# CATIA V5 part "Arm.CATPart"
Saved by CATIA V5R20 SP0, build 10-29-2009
Part number: Part1
Material "Plastic": density 1200 kg/m3, Young's modulus 2.2e+09 Pa, Poisson ratio 0.38, thermal expansion 6.84e-05 1/K
Bounding box of the stored display mesh (mm): x -46.402 to 0, y -86.485 to 14.997, z -29.997 to 131.328
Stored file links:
  C:\Users\user\SkyDrive\Stuff\cad\Instructables\Hand adapter\CATIA V5, STEP ,IGES Files\Arm.CATPart
  C:\Program Files\Dassault Systemes\B20\win_b64\reffiles\standard\MetricThinPitch.txt
  C:\Program Files\Dassault Systemes\B20\win_b64\startup\materials\Catalog.CATMaterial
  C:\Program Files\Dassault Systemes\B20\win_b64\reffiles\standard\MetricThickPitch.txt
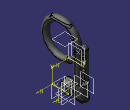
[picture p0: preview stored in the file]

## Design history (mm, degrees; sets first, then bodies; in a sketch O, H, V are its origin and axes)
Body1 (main body), material "Plastic"
  Sketch1 on xy-plane, origin (0, 0, 0), H (1, 0, 0), V (0, 1, 0)
    circle A1 centre (-31.4018, 0) radius 15
    radius A1 = 15
  Pad1: profile Sketch1, direction (0, 0, 1), length 10
  Sketch2 on end face of Pad1, origin (0, 0, 10), H (1, 0, 0), V (0, 1, 0)
    circle A1 centre (-23.9018, 0) radius 7.5
    point P1 (-23.9018, 0)
    circle A2 centre (-38.9018, 0) radius 7.5
    point P2 (-38.9018, 0)
    point P3 (-31.4018, 0)
    reference projected circle E1 centre (-31.4018, 0) radius 15 from edge [face of Pad1 from Sketch1.A1 | end face of Pad1]
    radius A1 = 7.5
    radius A2 = 7.5
    coincidence: P1 H, P2 H, P3 H
    tangency: A2 A1
    concentricity: P3 E1
    equidistance: P2 P1 P3
  Pad2: profile Sketch2, direction (0, 0, 1), length 65
  Plane1: type Offset, RefPlane zx-plane, Offset -7.5
  Sketch3 on Plane1, origin (0, -7.5, 0), H (-1, 0, 0), V (0, 0, 1)
    reference projected line E1 (16.4018, 10) -> (31.4018, 10) from edge [end face of Pad1 | face of Pad2 from Sketch2.A1]
    construction line L1 (31.4018, 75) -> (31.4018, 21.2562)
    spline S1 through (31.4018, 42.5) (36.4018, 50) (31.4018, 57.5) (26.4018, 50) (31.4018, 42.5)
    construction line L2 (93.6923, 50) -> (-93.4071, 50)
    construction line L3 (100.8473, 35) -> (-86.2521, 35)
    spline S2 through (31.4018, 31) (34.9018, 35) (31.4018, 39) (27.9018, 35) (31.4018, 31)
    line L4 (33.9018, 25) -> (28.9018, 25)
    line L5 (28.9018, 25) -> (28.9018, 15)
    line L6 (28.9018, 15) -> (33.9018, 15)
    line L7 (33.9018, 15) -> (33.9018, 25)
    construction line L8 (109.543, 20) -> (-92.7825, 20)
    point P16 (31.4018, 65)
    point P17 (31.4018, 60.9585)
    point P18 (34.9018, 62.9793)
    point P19 (34.9018, 67.0207)
    point P20 (31.4018, 69.0415)
    point P21 (27.9018, 67.0207)
    point P22 (27.9018, 62.9793)
    point P23 (33.1518, 61.9689)
    line L9 (31.4018, 60.9585) -> (34.9018, 62.9793)
    line L10 (34.9018, 62.9793) -> (34.9018, 67.0207)
    line L11 (34.9018, 67.0207) -> (31.4018, 69.0415)
    line L12 (31.4018, 69.0415) -> (27.9018, 67.0207)
    line L13 (27.9018, 67.0207) -> (27.9018, 62.9793)
    line L14 (27.9018, 62.9793) -> (31.4018, 60.9585)
    construction line L15 (31.4018, 65) -> (33.1518, 61.9689)
    construction circle A1 centre (31.4018, 65) radius 4.0415
    construction arc A2 centre (27.9018, 67.0207) radius 4.0415 from (31.4018, 69.0415) to (27.9018, 62.9793) cw
    construction arc A3 centre (34.9018, 62.9793) radius 4.0415 from (34.9018, 67.0207) to (31.4018, 60.9585) ccw
    point P24 (31.4018, 42.5)
    point P25 (31.4018, 57.5)
    point P26 (31.4018, 42.5)
    point P27 (36.4018, 50)
    point P28 (26.4018, 50)
    point P29 (34.9018, 35)
    point P30 (27.9018, 35)
    point P31 (31.4018, 39)
    point P32 (31.4018, 31)
    point P33 (31.4018, 31)
    distance P27 P28 = 10
    distance P25 P26 = 15
    distance P29 P30 = 7
    distance P31 P32 = 8
    length L4 = 5
    distance L4 L6 = 10
    distance L8 E1 = 10
    distance L3 L8 = 15
    distance L2 L3 = 15
    length L15 = 3.5
    distance P16 L2 = 15
    vertical: L1 V, L5 V, L7 V
    coincidence: P24 L1, P25 L1, P26 P24, P27 L2, P28 L2, P29 L3, P30 L3, P32 P33, P32 L1, P16 L1, A1 P17, A1 P18, A1 P19, A1 P20, A1 P21, A1 P22, A2 P16, A3 P16, P20 L1
    symmetry: P27 P28 L1, P25 P26 L2, P31 P32 L3, P29 P30 L1, L7 L5 L1, L4 L6 L8
    horizontal: L2 H, L4 H, L6 H, L8 H
    midpoint: P23 L9
    parallelism: L9 L12
  Pocket1: profile Sketch3, direction (0, 1, 0), through (limit type 3)
  Plane2: type Offset, RefPlane zx-plane, Offset -25
  Sketch4 on end face of Pad2, origin (0, 0, 75), H (1, 0, 0), V (0, 1, 0)
    point P1 (-23.9018, 0)
    reference projected circle E1 centre (-23.9018, 0) radius 7.5 from edge [face of Pad2 from Sketch2.A1 | end face of Pad2]
    concentricity: E1 P1
  Sketch5 on start face of Pad1, origin (0, 0, 0), H (1, 0, 0), V (0, -1, 0)
    circle A1 centre (-31.4018, 0) radius 15
    reference projected circle E1 centre (-31.4018, 0) radius 15 from edge [start face of Pad1 | face of Pad1 from Sketch1.A1]
    radius A1 = 15
    concentricity: A1 E1
  Sketch6 on start face of Pad1, origin (0, 0, 0), H (1, 0, 0), V (0, -1, 0)
    point P1 (-31.4018, 0)
    reference projected circle E1 centre (-31.4018, 0) radius 15 from edge [start face of Pad1 | face of Pad1 from Sketch1.A1]
    coincidence: P1 H
    concentricity: P1 E1
  Plane3: type OffsetPt, RefPlane yz-plane, RefPoint Sketch6
  Sketch7 on Plane3, origin (-31.4018, 0, 0), H (0, 1, 0), V (0, 0, 1)
    line L1 (0, 0) -> (0, -15)
    reference projected point E1 (0, 0) from Sketch6
    line L2 (0, -15) -> (-40, -15)
    length L1 = 15
    length L2 = 40
    vertical: L1 V
    coincidence: E1 L1
    horizontal: L2 H
  Rib1: profile Sketch5, centre curve Sketch7
  Plane4: type OffsetPt, RefPlane yz-plane, RefPoint Sketch4
  Sketch8 on end face of Pad2, origin (0, 0, 75), H (1, 0, 0), V (0, 1, 0)
    circle A1 centre (-23.9018, 0) radius 7.5
    point P1 (-23.9018, 0)
    reference projected point E1 (-23.9018, 0) from Sketch4
    radius A1 = 7.5
    coincidence: P1 H
    concentricity: E1 A1
  Sketch9 on Plane4, origin (-23.9018, 0, 0), H (0, 1, 0), V (0, 0, 1)
    arc A1 centre (-39.7571, 84.4017) radius 40 from (0, 80) to (-20, 49.6215) ccw
    construction line L1 (0, 139.5959) -> (0, 51.5037)
    point P2 (0, 139.5959)
    reference projected point E1 (0, 75) from Sketch4
    line L2 (0, 75) -> (0, 80)
    point P4 (0, 75)
    point P5 (0, 80)
    reference projected point E2 (0, 75) from Sketch4
    point P6 (-20, 49.6215)
    point P7 (0, 80)
    radius A1 = 40
    length L2 = 5
    distance P6 L1 = 20
    coincidence: P2 V, L1 E1, P4 L1, P5 A1, P4 E2, L1 P7, P5 P7
    vertical: L1 V, L2 V
  Rib2: profile Sketch8, centre curve Sketch9
  Sketch10 on face of Rib2, origin (0, 7.9366, 0.4422), H (-1, 0, 0), V (0, -0.4939, 0.8695)
    arc A1 centre (23.9018, 56.5603) radius 7.5 from (23.9018, 64.0603) to (23.9018, 49.0603) ccw
    point P1 (23.9018, 56.5603)
    reference projected circle E1 centre (23.9018, 56.5603) radius 7.5 from edge [face of Rib2 | face of Rib2]
    line L1 (23.9018, 64.0603) -> (23.9018, 49.0603)
    point P2 (23.9018, 52.8966)
    point P3 (23.9018, 60.2239)
    radius A1 = 7.5
    concentricity: A1 E1
    vertical: L1 V
    equidistance: P2 P3 P1
  Shaft1: profile Sketch10, axis Sketch10.L1, angle 360
  Sketch11 on end face of Pad2, origin (0, 0, 75), H (1, 0, 0), V (0, 1, 0)
    line L1 (-46.4018, 0) -> (-31.4018, 0)
    arc A1 centre (-38.9018, 0) radius 7.5 from (-31.4018, 0) to (-46.4018, 0) ccw
    point P1 (-38.9018, 0)
    reference projected circle E1 centre (-38.9018, 0) radius 7.5 from edge [face of Pad2 from Sketch2.A2 | end face of Pad2]
    radius A1 = 7.5
    horizontal: L1 H
    coincidence: P1 L1
    concentricity: A1 E1
  Shaft2: profile Sketch11, axis Sketch11.L1, angle 180
  Sketch12 on face of Rib1, origin (0, -40, 0), H (1, 0, 0), V (0, 0, 1)
    point P1 (-31.4018, -15)
    reference projected circle E1 centre (-31.4018, -15) radius 15 from edge [face of Rib1 | face of Rib1]
    concentricity: P1 E1
  Plane5: type OffsetPt, RefPlane xy-plane, RefPoint Sketch12
  Plane6: type Offset, RefPlane Plane3, Offset -15
  Plane7: type Offset, RefPlane Plane4, Offset 7.5
  Sketch13 on Plane7, origin (-16.4018, 0, 0), H (0, 1, 0), V (0, 0, 1)
    line L1 (-63.5987, 125.8143) -> (-13.5987, 125.8143)
    line L2 (-13.5987, 125.8143) -> (-13.5987, 120.8143)
    line L3 (-13.5987, 120.8143) -> (-63.5987, 120.8143)
    line L4 (-63.5987, 120.8143) -> (-63.5987, 125.8143)
    length L1 = 50
    length L2 = 5
    horizontal: L1 H, L3 H
    vertical: L2 V, L4 V
  Pocket2: profile Sketch13, direction (-1, 0, 0), length 8
  Fillet1: radius 6, on edge [face of Rib1 | face of Rib1]
  Sketch14 on Plane6, origin (-46.4018, 0, 0), H (0, 1, 0), V (0, 0, 1)
    line L1 (-15, -2.5) -> (-40, -2.5)
    line L2 (-40, -2.5) -> (-40, -27.5)
    line L3 (-40, -27.5) -> (-15, -27.5)
    line L4 (-15, -27.5) -> (-15, -2.5)
    point P2 (-40, -2.5)
    point P3 (-40, -27.5)
    reference projected point E1 (-40, -15) from Sketch12.P1
    length L2 = 25
    length L3 = 25
    horizontal: L1 H, L3 H
    vertical: L2 V, L4 V
    equidistance: P3 P2 E1
    coincidence: L2 E1
  Pocket3: profile Sketch14, direction (1, 0, 0), length 5
  Sketch15 on Plane7, origin (-16.4018, 0, 0), H (0, 1, 0), V (0, 0, 1)
    reference projected point E1 (-40, -15) from Sketch12.P1
    line L1 (-40, -2.5) -> (-15, -2.5)
    line L2 (-15, -2.5) -> (-15, -27.5)
    line L3 (-15, -27.5) -> (-40, -27.5)
    line L4 (-40, -27.5) -> (-40, -2.5)
    length L2 = 25
    length L1 = 25
    horizontal: L1 H, L3 H
    vertical: L2 V, L4 V
    midpoint: E1 L4
    coincidence: E1 L4
  Pocket4: profile Sketch15, direction (-1, 0, 0), length 5
  Sketch16 on end face of Pocket3, origin (-41.4018, -22.9671, -18.1896), H (0, 1, 0), V (0, 0, -1)
    point P1 (-4.5329, -3.1896)
    reference projected line E1 (-17.0329, -14.37) -> (-17.0329, 7.9907) from edge [end face of Pocket3 | face of Rib1]
    reference projected line E2 (7.9671, -13.9039) -> (7.9671, 7.9907) from edge [face of Rib1 | face of Pocket3 from Sketch14.L4]
    reference projected line E3 (-17.0329, 7.9907) -> (7.9671, 7.9907) from edge [end face of Pocket3 | face of Rib1]
    reference projected line E4 (-17.0329, -14.37) -> (7.3147, -14.37) from edge [face of Rib1 | end face of Pocket3]
    equidistance: E1 E2 P1, E3 E4 P1
  Hole1: placed by Sketch16, at (-41.4018, -27.5, -15) direction (1, 0, 0), diameter 8, through (limit type 3)
  Sketch17 on Plane7, origin (-16.4018, 0, 0), H (0, 1, 0), V (0, 0, 1)
    point P1 (0, 75)
    point P2 (4, 75)
    point P3 (2, 78.4641)
    point P4 (-2, 78.4641)
    point P5 (-4, 75)
    point P6 (-2, 71.5359)
    point P7 (2, 71.5359)
    point P8 (3, 76.7321)
    line L1 (4, 75) -> (2, 78.4641)
    line L2 (2, 78.4641) -> (-2, 78.4641)
    line L3 (-2, 78.4641) -> (-4, 75)
    line L4 (-4, 75) -> (-2, 71.5359)
    line L5 (-2, 71.5359) -> (2, 71.5359)
    line L6 (2, 71.5359) -> (4, 75)
    construction line L7 (0, 75) -> (3, 76.7321)
    construction circle A1 centre (0, 75) radius 4
    construction arc A2 centre (-2, 71.5359) radius 4 from (-4, 75) to (2, 71.5359) cw
    construction arc A3 centre (2, 78.4641) radius 4 from (-2, 78.4641) to (4, 75) ccw
    reference projected line E1 (-15, 10) -> (15, 10) from edge [face of Rib1 | end face of Pad1]
    point P9 (-15, 10)
    point P10 (15, 10)
    radius A2 = 4
    distance P1 E1 = 65
    coincidence: P1 V, A1 P2, A1 P3, A1 P4, A1 P5, A1 P6, A1 P7, A2 P1, A3 P1
    midpoint: P8 L1
    parallelism: L1 L4, L5 E1
    equidistance: P10 P9 P1
  Pocket5: profile Sketch17, direction (-1, 0, 0), length 10
  Sketch18 on Plane7, origin (-16.4018, 0, 0), H (0, 1, 0), V (0, 0, 1)
    circle A1 centre (-5, 104.5804) radius 2.5
    point P1 (-5, 104.5804)
    construction line L1 (0, 95.8845) -> (0, 52.9037)
    point P2 (0, 95.8845)
    reference projected point E1 (0, 75) from Sketch4
    radius A1 = 2.5
    distance P1 E1 = 30
    distance P1 L1 = 5
    coincidence: P2 V
    vertical: L1 V
  Pad3: profile Sketch18, direction (1, 0, 0), length 5, mirrored extent
  Sketch19 on end face of Pad3, origin (-11.4018, 0, 0), H (0, 1, 0), V (0, 0, 1)
    projected circle E1 centre (-5, 104.5804) radius 2.5 from edge [face of Pad3 from Sketch18.A1 | end face of Pad3]
    projected arc E2 centre (-5, 104.5804) radius 2.5 from (-5, 107.0804) to (-5, 102.0804) ccw from edge [face of Pad3 from Sketch18.A1 | end face of Pad3]
    line L1 (-5, 107.0804) -> (-5, 102.0804)
    point P1 (-5, 102.0804)
    point P2 (-5, 107.0804)
    point P3 (-5, 107.0804)
    point P4 (-5, 102.0804)
    vertical: L1 V
    coincidence: L1 P1, L1 P2, E1 P3, E1 P4, P1 P4, P2 P3
  Shaft3: profile Sketch19, axis Sketch19.L1, angle 180
  Fillet2: radius 3, on edge [face of Rib1 | face of Rib1]
  Fillet3: radius 3, on edge [face of Rib1 | face of Rib1]
  Sketch20 on Plane7, origin (-16.4018, 0, 0), H (0, 1, 0), V (0, 0, 1)
    arc A1 centre (0, 65) radius 3 from (2.958, 65.5) to (-2.958, 65.5) ccw
    point P1 (0, 65)
    line L1 (-4, 65.5) -> (-2.958, 65.5)
    line L2 (4, 65.5) -> (4, 64.5)
    line L3 (4, 64.5) -> (2.958, 64.5)
    line L4 (-4, 64.5) -> (-4, 65.5)
    point P4 (4, 64.5)
    point P5 (-4, 64.5)
    reference projected line E1 (-15, 10) -> (15, 10) from edge [face of Rib1 | end face of Pad1]
    point P9 (2.958, 65.5)
    arc A2 centre (0, 65) radius 3 from (-2.958, 64.5) to (2.958, 64.5) ccw
    point P11 (-2.958, 64.5)
    line L5 (-2.958, 64.5) -> (-4, 64.5)
    line L6 (2.958, 65.5) -> (4, 65.5)
    radius A1 = 3
    length L2 = 1
    distance E1 P1 = 55
    distance P4 P5 = 8
    coincidence: P1 V, L1 P9, L3 P11, A1 A2, L3 L5, L1 L6
    horizontal: L1 H, L3 H, L5 H, L6 H
    vertical: L2 V, L4 V
    equidistance: L4 L2 P1, L1 L3 P1
  Pocket6: profile Sketch20, direction (-1, 0, 0), length 10
  Plane8: type Offset, RefPlane Plane5, Offset 94
  Sketch21 on Plane8, origin (0, 0, 79), H (1, 0, 0), V (0, 1, 0)
    line L1 (-31.6518, 1) -> (-31.1518, 1)
    line L2 (-31.1518, 1) -> (-31.1518, -1)
    line L3 (-31.1518, -1) -> (-31.6518, -1)
    line L4 (-31.6518, -1) -> (-31.6518, 1)
    reference projected point E1 (-31.4018, 0) from Sketch6
    reference projected point E2 (-31.4018, 0) from Sketch6
    length L1 = 0.5
    length L2 = 2
    horizontal: L1 H, L3 H
    vertical: L2 V, L4 V
    equidistance: L4 L2 E1, L1 L3 E2
  Pocket7: profile Sketch21, direction (0, 0, -1), length 69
